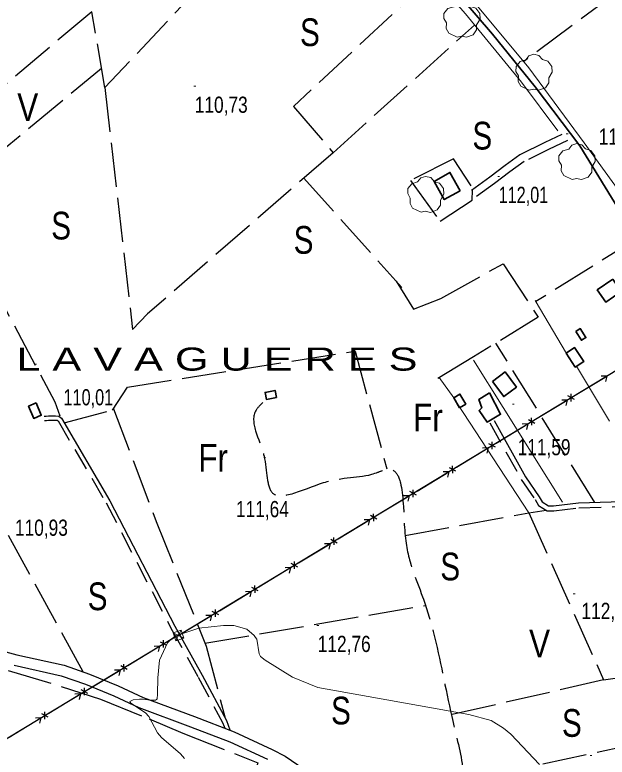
# Model space of a CAD drawing. Extents: x 483840 to 488445, y 4386047 to 4389027.
# Drawn here: x 485701.7 to 486022, y 4387565.7 to 4387967.4 of the extents above; entities that cross this region are included whole.
import ezdxf
from ezdxf.enums import TextEntityAlignment as Align

# ---------------------------------------------------------------- set-up
doc = ezdxf.new("R2010")
doc.units = 0
doc.header["$LTSCALE"] = 4
doc.linetypes.add('LONG_DASHED', pattern=[7.5, 6, -1.5])
doc.linetypes.add('MEDIUM_DASHED', pattern=[4.5, 3, -1.5])
for name, color, linetype, lineweight in [('25', 7, 'LONG_DASHED', 25), ('29', 7, 'Continuous', 13), ('36', 7, 'Continuous', 25), ('38', 7, 'Continuous', 25), ('43', 7, 'Continuous', 25), ('47', 7, 'Continuous', 35), ('51', 7, 'Continuous', 13), ('6', 7, 'Continuous', 35), ('7', 7, 'Continuous', 13), ('9', 7, 'Continuous', 13)]:
    doc.layers.add(name, color=color, linetype=linetype, lineweight=lineweight)
doc.layers.add('31', color=7, linetype='Continuous')
doc.layers.add('5', color=7, linetype='Continuous')

msp = doc.modelspace()

# ---------------------------------------------------------------- linework, layer by layer
at = {"layer": '25'}
for p, q in [((485873.83, 4387892.79), (485950.33, 4387961.88)), ((485662.86, 4387867.64), (485748.54, 4387938.59)), ((485750.37, 4387927.99), (485765.36, 4387797.12)), ((485857.96, 4387879), (485911, 4387819.86)), ((486039.73, 4387847.35), (485983.43, 4387812.19)), ((485765.36, 4387797.12), (485773.45, 4387805.53)), ((485738.53, 4387611.84), (485640.55, 4387791.09)), ((486015.46, 4387703.54), (485961.84, 4387789.66)), ((485723.27, 4387757.89), (485725.91, 4387750.4)), ((485804.5, 4387627.33), (485923.63, 4387647.8))]:
    msp.add_line(p, q, dxfattribs=at)
for points in [[(486253.47, 4388147.49), (486195.74, 4388104.93), (485976.9, 4387942.09)], [(485866.37, 4388051.37), (485750.37, 4387927.99), (485743.25, 4387969.09), (485649.76, 4387890.09), (485568.47, 4387977.38)], [(485927.75, 4387988.11), (485852.41, 4387917.81), (485873.83, 4387892.79), (485773.45, 4387805.53)], [(485649.76, 4387890.09), (485687.38, 4387825.57), (485723.27, 4387757.89)], [(485948.49, 4387874.83), (485938.87, 4387889.37), (485915.71, 4387877.7), (485931.65, 4387855.67), (485949.03, 4387867.03), (485949.25, 4387872.51)], [(485932.17, 4387813.97), (485965.74, 4387832.7), (485984.77, 4387803.7)], [(485907.95, 4387823.27), (485917.33, 4387808.06), (485932.17, 4387813.97)], [(485984.77, 4387803.7), (485949.75, 4387782.24), (485930.52, 4387770.66)], [(485728.25, 4387746.69), (485754.54, 4387753.52), (485762.53, 4387765.94), (485885.71, 4387785.41), (485902.81, 4387721.76)], [(485754.97, 4387754.2), (485778.14, 4387693.15), (485805.09, 4387625.83), (485815.38, 4387586.76)], [(485912.75, 4387685.62), (485979.61, 4387697.92), (485989.05, 4387699.41)], [(485979.61, 4387697.92), (486020.11, 4387607.45), (485937.78, 4387588.6)], [(486020.11, 4387607.45), (486080.72, 4387616.63), (486098.81, 4387585.68), (485944.62, 4387552.91)], [(485698.12, 4387612.51), (485726.66, 4387604), (485747.95, 4387597.01), (485774.36, 4387586.43), (485792.48, 4387578.67), (485833.07, 4387562.7), (485811.81, 4387492.32), (485815.11, 4387492.58)]]:
    msp.add_lwpolyline(points, dxfattribs=at)
at = {"layer": '29'}
for points in [[(485940.95, 4387955.35), (485936.41, 4387957.47), (485935, 4387960.01), (485935.1, 4387962.99), (485933.73, 4387965.4), (485933.77, 4387968.15), (485935.93, 4387970.75), (485939.12, 4387971.75), (485940.77, 4387973.94), (485943.34, 4387974.77), (485946.2, 4387974.12), (485948.15, 4387971.85), (485950.96, 4387971.03), (485953.09, 4387968.18), (485953.33, 4387965.05), (485951.45, 4387961.9), (485951.45, 4387959.22), (485949.63, 4387956.61), (485946.01, 4387955.27), (485943.24, 4387955.9)], [(485979.93, 4387926.68), (485975.39, 4387928.8), (485973.98, 4387931.34), (485974.08, 4387934.32), (485972.71, 4387936.73), (485972.75, 4387939.48), (485974.91, 4387942.08), (485978.1, 4387943.08), (485979.75, 4387945.27), (485982.32, 4387946.1), (485985.18, 4387945.45), (485987.13, 4387943.18), (485989.94, 4387942.36), (485992.07, 4387939.51), (485992.31, 4387936.38), (485990.43, 4387933.23), (485990.43, 4387930.55), (485988.61, 4387927.94), (485984.99, 4387926.6), (485982.22, 4387927.23)], [(486003.18, 4387878.34), (485998.64, 4387880.46), (485997.23, 4387883), (485997.33, 4387885.98), (485995.96, 4387888.39), (485996, 4387891.14), (485998.16, 4387893.74), (486001.35, 4387894.74), (486003, 4387896.93), (486005.57, 4387897.76), (486008.43, 4387897.11), (486010.38, 4387894.84), (486013.19, 4387894.02), (486015.32, 4387891.17), (486015.56, 4387888.04), (486013.68, 4387884.89), (486013.68, 4387882.21), (486011.86, 4387879.6), (486008.24, 4387878.26), (486005.47, 4387878.89)], [(485921.37, 4387860.57), (485916.83, 4387862.69), (485915.42, 4387865.23), (485915.52, 4387868.21), (485914.15, 4387870.62), (485914.19, 4387873.37), (485916.35, 4387875.97), (485919.54, 4387876.97), (485921.19, 4387879.16), (485923.76, 4387879.99), (485926.62, 4387879.34), (485928.57, 4387877.07), (485931.38, 4387876.25), (485933.51, 4387873.4), (485933.75, 4387870.27), (485931.87, 4387867.12), (485931.87, 4387864.44), (485930.05, 4387861.83), (485926.43, 4387860.49), (485923.66, 4387861.12)]]:
    msp.add_lwpolyline(points, close=True, dxfattribs=at)
at = {"layer": '36'}
for points in [[(485670.12, 4387629.89), (485702.71, 4387621.09), (485728.3, 4387615.4), (485741.97, 4387610.63), (485757.5, 4387604.24), (485770.99, 4387598.04), (485798.82, 4387587.68), (485820.32, 4387579.33), (485840.91, 4387569.8), (485847.92, 4387566.17), (485858.19, 4387559.27)], [(485701.31, 4387615.39), (485726.69, 4387609.74), (485739.89, 4387605.13), (485755.16, 4387598.85), (485768.73, 4387592.61), (485796.73, 4387582.18), (485818.02, 4387573.92), (485838.32, 4387564.52)]]:
    msp.add_lwpolyline(points, dxfattribs=at)
at = {"layer": '38'}
for points in [[(485997.59, 4387902.68), (485988.4, 4387898.3), (485974.88, 4387891.6), (485966.83, 4387885.85), (485958.58, 4387879.61), (485948.62, 4387872.33)], [(485717.55, 4387750.18), (485718.52, 4387750.24), (485719.81, 4387750.37), (485720.96, 4387750.36), (485722.08, 4387750.34), (485723.58, 4387750.4), (485725.38, 4387750.29), (485726.8, 4387749.16), (485753.07, 4387704.37), (485788.12, 4387636.63), (485802.9, 4387610.09), (485816.06, 4387585.48), (485817.01, 4387583.04), (485817.97, 4387580.42)], [(485960.89, 4387747.94), (485977.93, 4387717.41), (485985.34, 4387706.58), (485986.96, 4387703.89), (485990.41, 4387701.74), (485993.05, 4387701.71), (486006.57, 4387703.25), (486041.85, 4387704.39), (486059.4, 4387706.46), (486078.18, 4387709.34), (486082.78, 4387710.1), (486092.93, 4387711.3), (486104.45, 4387713.23), (486117.2, 4387717.45), (486136.41, 4387726.31), (486158.17, 4387737.62), (486171.63, 4387744.4), (486176.77, 4387747.06)]]:
    msp.add_lwpolyline(points, dxfattribs=at)
at = {"layer": '38', "linetype": 'MEDIUM_DASHED'}
for points in [[(486000.59, 4387899.38), (485990.27, 4387894.47), (485977.08, 4387887.93), (485969.35, 4387882.42), (485961.13, 4387876.19), (485951.13, 4387868.88)], [(485717.69, 4387747.88), (485718.7, 4387747.94), (485719.92, 4387748.06), (485720.92, 4387748.06), (485722.1, 4387748.03), (485723.56, 4387748.09), (485724.52, 4387748.04), (485725.03, 4387747.63), (485751.05, 4387703.25), (485786.09, 4387635.54), (485800.88, 4387608.98), (485813.97, 4387584.52), (485814.86, 4387582.23), (485815.19, 4387581.32)], [(485958.52, 4387746.61), (485975.62, 4387715.98), (485983.06, 4387705.11), (485984.97, 4387701.93), (485989.62, 4387699.04), (485993.18, 4387698.99), (486006.76, 4387700.54), (486042.06, 4387701.68), (486059.76, 4387703.77), (486078.61, 4387706.66), (486083.17, 4387707.41), (486093.32, 4387708.61), (486105.11, 4387710.59), (486118.19, 4387714.92), (486137.61, 4387723.87), (486159.41, 4387735.2), (486172.87, 4387741.98), (486178.82, 4387745.07)]]:
    msp.add_lwpolyline(points, dxfattribs=at)
at = {"layer": '38', "linetype": 'LONG_DASHED'}
msp.add_spline([(485835.79, 4387757.61), (485832.21, 4387753.53), (485836.43, 4387728.63), (485841.09, 4387708.61), (485870.67, 4387714.86), (485898.06, 4387719.87), (485902.21, 4387721.39), (485912.8, 4387685.45), (485922.23, 4387652.37), (485927.96, 4387633.68), (485937.96, 4387587.76), (485943.87, 4387560.52), (485945.58, 4387543.23)], degree=3, dxfattribs=at)
at = {"layer": '43'}
for p, q in [((486004.74, 4387761.53), (486021.85, 4387771.89)), ((486021.85, 4387771.89), (486018.85, 4387771.83)), ((486021.85, 4387771.89), (486021.14, 4387768.98)), ((486004.36, 4387759.26), (486000.86, 4387761.19)), ((486002.65, 4387758.23), (486002.57, 4387762.22)), ((485983.36, 4387748.58), (486000.47, 4387758.94)), ((486000.47, 4387758.94), (485997.47, 4387758.87)), ((486000.47, 4387758.94), (485999.75, 4387756.03)), ((485982.98, 4387746.31), (485979.48, 4387748.23)), ((485981.27, 4387745.27), (485981.19, 4387749.27)), ((485961.98, 4387735.62), (485979.09, 4387745.98)), ((485979.09, 4387745.98), (485976.09, 4387745.92)), ((485979.09, 4387745.98), (485978.37, 4387743.07)), ((485959.89, 4387732.32), (485959.81, 4387736.31)), ((485940.6, 4387722.67), (485957.71, 4387733.03)), ((485957.71, 4387733.03), (485954.7, 4387732.96)), ((485957.71, 4387733.03), (485956.99, 4387730.12)), ((485961.6, 4387733.35), (485958.1, 4387735.28)), ((485919.22, 4387709.71), (485936.32, 4387720.07)), ((485936.32, 4387720.07), (485933.32, 4387720.01)), ((485936.32, 4387720.07), (485935.61, 4387717.16)), ((485940.22, 4387720.4), (485936.72, 4387722.32)), ((485938.51, 4387719.36), (485938.43, 4387723.36)), ((485918.84, 4387707.44), (485915.33, 4387709.37)), ((485917.13, 4387706.41), (485917.04, 4387710.4)), ((485897.84, 4387696.76), (485914.94, 4387707.12)), ((485914.94, 4387707.12), (485911.94, 4387707.05)), ((485914.94, 4387707.12), (485914.23, 4387704.21)), ((485897.46, 4387694.49), (485893.95, 4387696.41)), ((485895.75, 4387693.45), (485895.66, 4387697.45)), ((485876.46, 4387683.8), (485893.56, 4387694.16)), ((485893.56, 4387694.16), (485890.56, 4387694.1)), ((485893.56, 4387694.16), (485892.85, 4387691.25)), ((485876.07, 4387681.53), (485872.57, 4387683.46)), ((485874.36, 4387680.5), (485874.28, 4387684.49)), ((485855.07, 4387670.85), (485872.18, 4387681.21)), ((485872.18, 4387681.21), (485869.18, 4387681.14)), ((485872.18, 4387681.21), (485871.47, 4387678.3)), ((485852.98, 4387667.54), (485852.9, 4387671.54)), ((485833.69, 4387657.89), (485850.8, 4387668.25)), ((485850.8, 4387668.25), (485847.8, 4387668.19)), ((485850.8, 4387668.25), (485850.08, 4387665.34)), ((485854.69, 4387668.58), (485851.19, 4387670.5)), ((485812.31, 4387644.94), (485829.42, 4387655.3)), ((485829.42, 4387655.3), (485826.42, 4387655.23)), ((485829.42, 4387655.3), (485828.7, 4387652.39)), ((485833.31, 4387655.62), (485829.81, 4387657.55)), ((485831.6, 4387654.59), (485831.52, 4387658.58)), ((485811.93, 4387642.67), (485808.43, 4387644.59)), ((485810.22, 4387641.63), (485810.14, 4387645.63)), ((485790.93, 4387631.98), (485808.04, 4387642.34)), ((485808.04, 4387642.34), (485805.03, 4387642.28)), ((485808.04, 4387642.34), (485807.32, 4387639.43)), ((485784.25, 4387628.31), (485790.32, 4387631.98)), ((485783.86, 4387626.05), (485780.36, 4387627.97)), ((485782.15, 4387625.01), (485782.07, 4387629.01)), ((485762.85, 4387615.38), (485779.97, 4387625.73)), ((485779.97, 4387625.73), (485776.97, 4387625.66)), ((485779.97, 4387625.73), (485779.25, 4387622.81)), ((485762.47, 4387613.12), (485758.96, 4387615.04)), ((485760.75, 4387612.08), (485760.68, 4387616.08)), ((485741.45, 4387602.45), (485758.57, 4387612.8)), ((485758.57, 4387612.8), (485755.57, 4387612.74)), ((485758.57, 4387612.8), (485757.85, 4387609.89)), ((485739.36, 4387599.15), (485739.28, 4387603.15)), ((485720.05, 4387589.52), (485737.17, 4387599.87)), ((485737.17, 4387599.87), (485734.17, 4387599.81)), ((485737.17, 4387599.87), (485736.45, 4387596.96)), ((485741.07, 4387600.19), (485737.57, 4387602.12)), ((485698.66, 4387576.6), (485715.78, 4387586.94)), ((485715.78, 4387586.94), (485712.77, 4387586.88)), ((485715.78, 4387586.94), (485715.06, 4387584.03)), ((485719.67, 4387587.26), (485716.17, 4387589.19)), ((485717.96, 4387586.23), (485717.88, 4387590.22))]:
    msp.add_line(p, q, dxfattribs=at)
at = {"layer": '43', "lineweight": 13}
for p, q in [((485787.26, 4387632.92), (485793.04, 4387630.07)), ((485791.6, 4387634.37), (485788.7, 4387628.62))]:
    msp.add_line(p, q, dxfattribs=at)
at = {"layer": '43'}
for points in [[(485790.93, 4387631.98), (486094.33, 4387815.81), (486392.84, 4387991.71)], [(485163.39, 4387253.93), (485478.99, 4387443.87), (485790.32, 4387631.98)]]:
    msp.add_lwpolyline(points, dxfattribs=at)
at = {"layer": '43', "lineweight": 13}
msp.add_lwpolyline([(485787.26, 4387632.92), (485791.6, 4387634.37), (485793.04, 4387630.07), (485788.7, 4387628.62)], close=True, dxfattribs=at)
at = {"layer": '47'}
for points in [[(485942.57, 4387872.19), (485937, 4387882.09), (485928.42, 4387877.27), (485933.96, 4387867.38)], [(486025.09, 4387824.31), (486016.73, 4387818.55), (486021.31, 4387811.9), (486029.67, 4387817.66)], [(486005.1, 4387796.08), (486008.12, 4387791.26), (486010.53, 4387792.77), (486007.51, 4387797.59)], [(485999.83, 4387784.37), (486004.8, 4387776.75), (486009.37, 4387779.73), (486004.4, 4387787.35)], [(485959.99, 4387769.04), (485966.1, 4387760.83), (485972.93, 4387765.92), (485966.82, 4387774.13)], [(485843.11, 4387760.35), (485837.72, 4387759.32), (485837, 4387763.07), (485842.39, 4387764.1)], [(485939.08, 4387760.18), (485942.25, 4387754.77), (485945.56, 4387756.71), (485942.39, 4387762.12)], [(485958.33, 4387762.83), (485964.39, 4387751.26), (485957.12, 4387747.02), (485952.79, 4387753.23), (485954.23, 4387754.64), (485952.65, 4387759.24)], [(485713.18, 4387757.34), (485715.97, 4387750.68), (485711.86, 4387748.95), (485709.07, 4387755.61)]]:
    msp.add_lwpolyline(points, close=True, dxfattribs=at)
at = {"layer": '51'}
for p, q in [((485983.05, 4387812.83), (485999.99, 4387784.14)), ((485949.8, 4387780.44), (485997.92, 4387703.59)), ((486005.51, 4387777.21), (486023.25, 4387747.48)), ((485939.08, 4387760.18), (485931.26, 4387771.11)), ((485979.61, 4387697.92), (485941.06, 4387756.82))]:
    msp.add_line(p, q, dxfattribs=at)
for points in [[(485793.72, 4388162.1), (485801.18, 4388138.64), (485813.83, 4388111.28), (485822.71, 4388098.09), (485833.89, 4388084.37), (485853.74, 4388063.03), (485872.38, 4388045.81), (485891.31, 4388027.31), (485918.44, 4387998.78), (485945.34, 4387967.92), (485975.78, 4387930.98), (485995.33, 4387904.54)], [(486055.38, 4387837.5), (486046.51, 4387846.86), (486032.37, 4387866.72), (486009.59, 4387898.11), (485979.75, 4387938.64), (485951.94, 4387972.13), (485930.82, 4387996.62), (485910.45, 4388018.27)]]:
    msp.add_lwpolyline(points, dxfattribs=at)
at = {"layer": '6'}
msp.add_lwpolyline([(485912.17, 4388011.78), (485935.61, 4387985.33), (485960.06, 4387956.84), (485983.16, 4387928.35), (486007.28, 4387896.47), (486027.88, 4387862.88), (486044.27, 4387841.38), (486049.75, 4387833.89), (486058.02, 4387825.05), (486074.09, 4387815.1), (486088.73, 4387807.17), (486116.23, 4387792.4)], dxfattribs=at)
at = {"layer": '7'}
for p, q in [((485798.48, 4387928.74), (485799.48, 4387928.74)), ((485999.93, 4387902.97), (486000.93, 4387902.97)), ((485962.84, 4387879.95), (485963.84, 4387879.95)), ((485712.3, 4387778.43), (485713.3, 4387778.43)), ((485970.79, 4387756.64), (485971.79, 4387756.64)), ((485836.29, 4387727.8), (485837.29, 4387727.8)), ((486003.69, 4387654.12), (486004.69, 4387654.12)), ((485865, 4387636.97), (485866, 4387636.97)), ((486012.79, 4387566.57), (486013.79, 4387566.57))]:
    msp.add_line(p, q, dxfattribs=at)
at = {"layer": '9'}
msp.add_lwpolyline([(485985.47, 4387561.74), (485969.89, 4387578.15), (485965.99, 4387581.43), (485959.26, 4387585.51), (485947.26, 4387588.78), (485865.57, 4387603.3), (485851.89, 4387608.99), (485837.01, 4387618.2), (485834.59, 4387620.1), (485834.15, 4387620.83), (485833.8, 4387621.66), (485832.49, 4387629.48), (485831.89, 4387630.53), (485831.14, 4387631.54), (485827.11, 4387634.88), (485820.07, 4387636.87), (485814.46, 4387637.02), (485801.26, 4387635.57), (485788.76, 4387631.33), (485786.24, 4387629.57), (485784.14, 4387627.55), (485779.99, 4387618.14), (485778.93, 4387608.57), (485778.87, 4387599.74), (485778.6, 4387597.23), (485778.23, 4387596.82), (485777.72, 4387596.53), (485774.81, 4387596.52), (485771.11, 4387597.04), (485769.11, 4387597.1), (485765.61, 4387596.78), (485763.87, 4387595.8), (485763.98, 4387595.39), (485764.35, 4387594.92), (485772.32, 4387589.72), (485774.19, 4387587.72), (485778.89, 4387578.92), (485780.98, 4387576.41), (485791.26, 4387567.44), (485793.36, 4387564.89)], dxfattribs=at)

# ---------------------------------------------------------------- texts
at = {"layer": '31'}
for s, width, p in [('S', 0.8, (485861.28, 4387950.46)), ('V', 0.85, (485708.64, 4387909.91)), ('S', 0.8, (485954.52, 4387894.5)), ('S', 0.8, (485726.68, 4387845.83)), ('S', 0.8, (485857.84, 4387838.09)), ('Fr', 0.85, (485925.06, 4387741.98)), ('Fr', 0.85, (485808.92, 4387720.18)), ('S', 0.8, (485937.16, 4387661.36)), ('S', 0.8, (485746.42, 4387645.23)), ('V', 0.85, (485985.5, 4387619.7)), ('S', 0.8, (485878.05, 4387583.42)), ('S', 0.8, (486002.97, 4387576.7))]:
    msp.add_text(s, height=15, dxfattribs=dict(at, width=width)).set_placement(p, align=Align.CENTER)
at = {"layer": '5', "width": 1.4}
msp.add_text('S E S   C L A V A G U E R E S', height=12.49, dxfattribs=at).set_placement((485919.47, 4387774.85), align=Align.RIGHT)
at = {"layer": '7'}
for s, width, p in [('110,73', 0.8, (485798.98, 4387914.37)), ('112,65', 0.8, (486017.53, 4387897.15)), ('112,01', 0.75, (485963.34, 4387865.58)), ('110,01', 0.75, (485728.01, 4387756.07)), ('111,59', 0.8, (485973.63, 4387729.06)), ('111,64', 0.8, (485821.25, 4387695.56)), ('110,93', 0.8, (485701.7, 4387685.48)), ('112,95', 0.8, (486008.16, 4387640.47)), ('112,76', 0.8, (485865.5, 4387622.6))]:
    msp.add_text(s, height=8.75, dxfattribs=dict(at, width=width)).set_placement(p)

doc.saveas('drawing.dxf')
